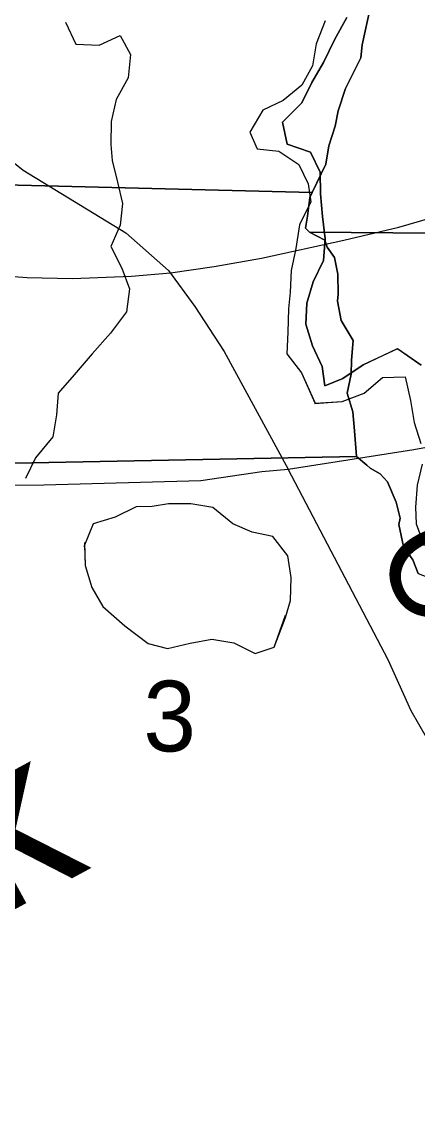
# Model space of a CAD drawing. Extents: x 1985906 to 2277390, y 930619 to 1324581.
# Drawn here: x 2082117 to 2083354, y 1127469 to 1130909 of the extents above; entities that cross this region are included whole.
import ezdxf

# ---------------------------------------------------------------- set-up
doc = ezdxf.new("R2010")
doc.units = 0
for name, color, linetype in [('GM_X_County_Road', 7, 'Continuous'), ('GM_X_County_Road_Text', 7, 'Continuous'), ('GM_X_Major_River', 7, 'Continuous'), ('GM_X_Minor_Lake', 7, 'Continuous'), ('GM_X_Minor_River', 7, 'Continuous'), ('GM_X_Minor_River_Text', 7, 'Continuous'), ('GM_X_Rail_Line', 7, 'Continuous'), ('GM_X_Section', 7, 'Continuous'), ('GM_X_Section_Text', 7, 'Continuous'), ('GM_X_State_Route', 7, 'Continuous')]:
    doc.layers.add(name, color=color, linetype=linetype)

msp = doc.modelspace()

# ---------------------------------------------------------------- linework, layer by layer
at = {"layer": 'GM_X_County_Road'}
for points in [[(2080321.6, 1131778.4), (2081331.8, 1131067.6), (2081436.5, 1130991.7), (2081601.5, 1130863.8), (2082121, 1130446.3), (2082442.1, 1130250), (2082575.4, 1130131.9), (2082657.3, 1130019.5), (2082748.8, 1129878.6), (2082948.8, 1129510.9)], [(2085479.8, 1124404.8), (2084882, 1125824.2), (2084152.5, 1127699.1), (2084069.5, 1127871.3), (2084006.9, 1127971.4), (2083751, 1128245.3), (2083381.2, 1128670.9), (2083333.5, 1128754.7), (2083261.2, 1128914.7), (2082948.8, 1129510.9)]]:
    msp.add_lwpolyline(points, dxfattribs=at)
at = {"layer": 'GM_X_Major_River'}
for points in [[(2083064.1, 1130913.2), (2083036.4, 1130840.8), (2083024.8, 1130772.6), (2082991.1, 1130712.2), (2082933.2, 1130663.7), (2082869.2, 1130633.2), (2082829.5, 1130564.8), (2082851.9, 1130512.8), (2082920.2, 1130505.1), (2082982.7, 1130463.4), (2083011.1, 1130403.4), (2083019.5, 1130347.3), (2082983.9, 1130274.8), (2082972.3, 1130200.5), (2082958.7, 1130132.2), (2082955.1, 1130064), (2082949.4, 1130011.8), (2082947.9, 1129939.6), (2082944.3, 1129871.4), (2082990.8, 1129811.5), (2083033, 1129716.7)], [(2083064.1, 1130913.2), (2083036.4, 1130840.8), (2083024.8, 1130772.6), (2082991.1, 1130712.2), (2082933.2, 1130663.7), (2082869.2, 1130633.2), (2082829.5, 1130564.8), (2082851.9, 1130512.8), (2082920.2, 1130505.1), (2082982.7, 1130463.4), (2083011.1, 1130403.4), (2083019.5, 1130347.3), (2082983.9, 1130274.8), (2082972.3, 1130200.5), (2082958.7, 1130132.2), (2082955.1, 1130064), (2082949.4, 1130011.8), (2082947.9, 1129939.6), (2082944.3, 1129871.4), (2082990.8, 1129811.5), (2083032.4, 1129717.9)], [(2083290.6, 1129887.4), (2083183.3, 1129836.7), (2083119.4, 1129794.2), (2083063.3, 1129771.8), (2083054.9, 1129831.9), (2083024.4, 1129895.9), (2083003.9, 1129964), (2083007.5, 1130030.2), (2083027.2, 1130096.6), (2083058.8, 1130162.9), (2083064.4, 1130231.2), (2083055.9, 1130301.3), (2083049.5, 1130371.5), (2083049, 1130439.7), (2083018.5, 1130501.7), (2082946.1, 1130527.4), (2082931.6, 1130595.5), (2082991.5, 1130656), (2083023.2, 1130720.4), (2083058.9, 1130782.8), (2083094.5, 1130855.2), (2083132.2, 1130923.7)], [(2083132.2, 1130923.7), (2083094.5, 1130855.2), (2083058.9, 1130782.8), (2083023.2, 1130720.4), (2082991.5, 1130656), (2082931.6, 1130595.5), (2082946.1, 1130527.4), (2083018.5, 1130501.7), (2083049, 1130439.7), (2083049.5, 1130371.5), (2083055.9, 1130301.3), (2083064.4, 1130231.2), (2083058.8, 1130162.9), (2083027.2, 1130096.6), (2083007.5, 1130030.2), (2083003.9, 1129964), (2083024.4, 1129895.9), (2083054.9, 1129831.9), (2083063.3, 1129771.8), (2083119.4, 1129794.2), (2083183.3, 1129836.7), (2083288.9, 1129886.6)], [(2083364, 1129835.8), (2083290.6, 1129887.4)], [(2083291.7, 1129886.6), (2083364, 1129835.8)], [(2083031, 1129716.5), (2083117.8, 1129722), (2083185.9, 1129748.4), (2083243.8, 1129796.9), (2083314, 1129799.3), (2083330.6, 1129725.2), (2083343, 1129657.1), (2083363.5, 1129591)], [(2083033, 1129716.7), (2083117.8, 1129722), (2083185.9, 1129748.4), (2083243.8, 1129796.9), (2083314, 1129799.3), (2083330.6, 1129725.2), (2083343, 1129657.1), (2083363.5, 1129591)], [(2083367.9, 1129526.8), (2083352.3, 1129460.6), (2083346.7, 1129392.3), (2083349.1, 1129340.2), (2083373.6, 1129272.1)], [(2083367.9, 1129526.8), (2083352.3, 1129460.6), (2083346.7, 1129392.3), (2083349.1, 1129340.2), (2083373.6, 1129272.1)]]:
    msp.add_lwpolyline(points, dxfattribs=at)
at = {"layer": 'GM_X_Minor_Lake'}
for points in [[(2082940.9, 1129047.1), (2082956.5, 1129099.4), (2082958, 1129171.8), (2082947.4, 1129240.1), (2082900.7, 1129300), (2082836.3, 1129313.6), (2082775.9, 1129339.2), (2082713.2, 1129391), (2082644.8, 1129402.6), (2082574.5, 1129402), (2082524.4, 1129393.6), (2082474.2, 1129393.2), (2082408.2, 1129360.5), (2082340, 1129339.9), (2082310.5, 1129267.3)], [(2082940.9, 1129047.1), (2082956.5, 1129099.4), (2082958, 1129171.8), (2082947.4, 1129240.1), (2082900.7, 1129300), (2082836.3, 1129313.6), (2082775.9, 1129339.2), (2082713.2, 1129391), (2082644.8, 1129402.6), (2082574.5, 1129402), (2082524.4, 1129393.6), (2082474.2, 1129393.2), (2082408.2, 1129360.5), (2082340, 1129339.9), (2082312.7, 1129272.7)], [(2082312.4, 1129281.4), (2082315, 1129209.1), (2082335.6, 1129140.9), (2082370.2, 1129080.9), (2082439, 1129021.1), (2082511.8, 1128965.4), (2082572.1, 1128949.8), (2082642.3, 1128966.4), (2082710.5, 1128979), (2082778.9, 1128967.4), (2082845.4, 1128933.8), (2082905.5, 1128954.3), (2082940, 1129054.4)], [(2082312.7, 1129272.7), (2082315, 1129209.1), (2082335.6, 1129140.9), (2082370.2, 1129080.9), (2082439, 1129021.1), (2082511.8, 1128965.4), (2082572.1, 1128949.8), (2082642.3, 1128966.4), (2082710.5, 1128979), (2082778.9, 1128967.4), (2082845.4, 1128933.8), (2082905.5, 1128954.3), (2082940.9, 1129047.1)]]:
    msp.add_lwpolyline(points, dxfattribs=at)
at = {"layer": 'GM_X_Minor_River'}
msp.add_lwpolyline([(2082253.3, 1130908.4), (2082285.9, 1130840.4), (2082358.2, 1130836.8), (2082424.2, 1130867.3), (2082456.7, 1130807.3), (2082449.1, 1130735.1), (2082411.4, 1130666.6), (2082395.8, 1130598.3), (2082394.3, 1130526.1), (2082398.6, 1130476), (2082415.1, 1130407.9), (2082431.6, 1130341.8), (2082424, 1130273.5), (2082394.3, 1130207.1), (2082428.8, 1130139.1), (2082453.3, 1130075.1), (2082443.8, 1130002.8), (2082394, 1129936.3), (2082336.2, 1129871.8), (2082280.5, 1129805.2), (2082230.7, 1129748.8), (2082225.1, 1129680.6), (2082213.5, 1129612.3), (2082159.7, 1129545.8), (2082128, 1129481.4)], dxfattribs=at)
at = {"layer": 'GM_X_Rail_Line'}
msp.add_lwpolyline([(2082006.4, 1130119.5), (2082133.6, 1130109.9), (2082274.6, 1130106.7), (2082459.3, 1130114.2), (2082581.1, 1130124.8), (2082717.8, 1130144.1), (2082865.3, 1130170.8), (2083122.7, 1130227.4), (2083294.7, 1130268), (2083399.3, 1130297.9), (2083508.3, 1130332.1), (2083645, 1130383.3), (2083762.5, 1130434.6), (2083869.3, 1130482.7), (2083990, 1130548.9), (2084073.3, 1130597), (2084162, 1130654.7), (2084259.2, 1130722), (2084341.5, 1130786), (2084426.9, 1130853.3), (2084513.4, 1130929.2)], dxfattribs=at)
at = {"layer": 'GM_X_Section'}
for points in [[(2083205.7, 1130956.4), (2083180.4, 1130837.5), (2083175.6, 1130796.9), (2083128.1, 1130700.8), (2083104.7, 1130631.8), (2083095.9, 1130583.1), (2083076.4, 1130522.3), (2083066.5, 1130464.2), (2083024.1, 1130376), (2080351.3, 1130442.8), (2080371.1, 1132115.1)], [(2085650.9, 1131985.2), (2085619.1, 1130230.7), (2083015, 1130252.4), (2083003, 1130264), (2083009.1, 1130301.8), (2083016.4, 1130359.9), (2083024.1, 1130376), (2083066.5, 1130464.2), (2083076.4, 1130522.3), (2083095.9, 1130583.1), (2083104.7, 1130631.8), (2083128.1, 1130700.8), (2083175.6, 1130796.9), (2083180.4, 1130837.5), (2083205.7, 1130956.4)], [(2083355.2, 1129184.2), (2083338.4, 1129227.3), (2083309.4, 1129268.9), (2083295, 1129337.6), (2083298.8, 1129357.9), (2083285.9, 1129407.7), (2083259.4, 1129471), (2083236, 1129496.5), (2083204.6, 1129513.9), (2083194.3, 1129522.7), (2083162.1, 1129550.3), (2083155.6, 1129630.4), (2083150.7, 1129690.1), (2083133.4, 1129748), (2083146, 1129807.4), (2083146.6, 1129852), (2083152.4, 1129912.7), (2083114.5, 1129975.9), (2083102.5, 1130036.6), (2083104.9, 1130058.2), (2083103.8, 1130120.3), (2083093.3, 1130172.8), (2083070.9, 1130205.1), (2083063.7, 1130226.6), (2083015, 1130252.4), (2085619.1, 1130230.7)]]:
    msp.add_lwpolyline(points, dxfattribs=at)
for points in [[(2083024.1, 1130376), (2083016.4, 1130359.9), (2083009.1, 1130301.8), (2083003, 1130264), (2083015, 1130252.4), (2083063.7, 1130226.6), (2083070.9, 1130205.1), (2083093.3, 1130172.8), (2083103.8, 1130120.3), (2083104.9, 1130058.2), (2083102.5, 1130036.6), (2083114.5, 1129975.9), (2083152.4, 1129912.7), (2083146.6, 1129852), (2083146, 1129807.4), (2083133.4, 1129748), (2083150.7, 1129690.1), (2083155.6, 1129630.4), (2083162.1, 1129550.3), (2081986.1, 1129527.8), (2081984.5, 1129324), (2080322.5, 1129328), (2080351.3, 1130442.8)], [(2081984.5, 1129324), (2081986.1, 1129527.8), (2083162.1, 1129550.3), (2083194.3, 1129522.7), (2083204.6, 1129513.9), (2083236, 1129496.5), (2083259.4, 1129471), (2083285.9, 1129407.7), (2083298.8, 1129357.9), (2083295, 1129337.6), (2083309.4, 1129268.9), (2083338.4, 1129227.3), (2083355.2, 1129184.2), (2083426.1, 1129157.5), (2083458.6, 1129048.4), (2083461.6, 1129031.1), (2083404.6, 1126764.8), (2082924.1, 1126765.8), (2081964.7, 1126767.8)]]:
    msp.add_lwpolyline(points, close=True, dxfattribs=at)
at = {"layer": 'GM_X_State_Route'}
msp.add_lwpolyline([(2080466.1, 1129469), (2081362, 1129459.5), (2082184.9, 1129461.4), (2082676.3, 1129474.7), (2082866.8, 1129503.3), (2082948.8, 1129510.9), (2083341.1, 1129571.9), (2083529.7, 1129606.2), (2083771.7, 1129646.2), (2083935.5, 1129669), (2084205.9, 1129680.5), (2085604.1, 1129650), (2086185.5, 1129636.1)], dxfattribs=at)

# ---------------------------------------------------------------- texts
at = {"layer": 'GM_X_County_Road_Text'}
msp.add_text('C', height=300, rotation=296.3416, dxfattribs=at).set_placement((2083216, 1129260.9))
at = {"layer": 'GM_X_Minor_River_Text'}
msp.add_text('Creek', height=500.22, rotation=28.4757, dxfattribs=at).set_placement((2080764.9, 1127412.6))
at = {"layer": 'GM_X_Section_Text'}
msp.add_text('3', height=221, rotation=0, dxfattribs=at).set_placement((2082496.4, 1128628))

doc.saveas('drawing.dxf')
